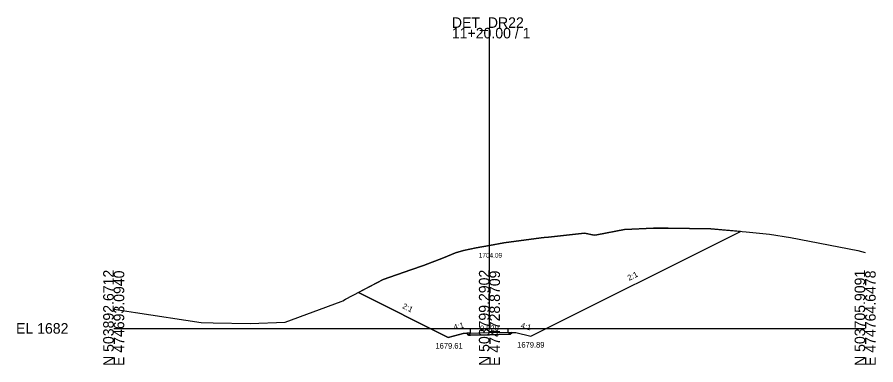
# Model space of a CAD drawing. Extents: x -26 to 1203, y -10 to 9633.
# Drawn here: x -25.7 to 202.8, y 2990.3 to 3082.8 of the extents above; entities that cross this region are included whole.
import ezdxf

# ---------------------------------------------------------------- set-up
doc = ezdxf.new("R2010")
doc.units = 0
for name, color, linetype in [('Exist Cross Section Cell', 7, 'Continuous'), ('Exist XS Center Line Elevation Label', 7, 'Continuous'), ('Exist XS Ground Line', 7, 'Continuous'), ('Prop XS Ditch Slope Text', 7, 'Continuous'), ('Prop XS Ditch Standard Text', 7, 'Continuous'), ('Prop XS Earthwork Shape', 7, 'Continuous'), ('Prop XS EOT Tick Mark', 7, 'Continuous'), ('Prop XS Finish Grade', 7, 'Continuous'), ('Prop XS Finish Grade Earthwork', 7, 'Continuous'), ('Prop XS Finish Grade Pavement', 7, 'Continuous'), ('Prop XS Pvmt Edge Slope', 7, 'Continuous'), ('Prop XS SE Text', 7, 'Continuous'), ('Prop XS Shoulder Borrow Shape', 7, 'Continuous'), ('Prop XS Side Slope Text', 7, 'Continuous'), ('Prop XS Subgrade Earthwork', 7, 'Continuous')]:
    doc.layers.add(name, color=color, linetype=linetype)

msp = doc.modelspace()

# ---------------------------------------------------------------- linework, layer by layer
at = {"layer": 'Exist Cross Section Cell'}
for p, q in [((100, 3000), (100, 3079.98)), ((0, 3000), (100, 3000)), ((100, 3000), (200, 3000))]:
    msp.add_line(p, q, dxfattribs=at)
at = {"layer": 'Exist XS Ground Line'}
msp.add_lwpolyline([(0, 3005.15), (5.82, 3004.23), (23.26, 3001.59), (26.46, 3001.48), (36.33, 3001.31), (45.67, 3001.68), (60.56, 3007.17), (60.99, 3007.35), (61.71, 3007.74), (71.7, 3013.04), (79.08, 3015.55), (82.41, 3016.78), (87.78, 3018.79), (90.98, 3020.09), (93.12, 3020.74), (96.44, 3021.44), (100, 3022.09), (103.83, 3022.8), (113.8, 3024.06), (114.54, 3024.17), (115.74, 3024.26), (125.26, 3025.31), (127.85, 3024.82), (128.6, 3024.93), (135.97, 3026.35), (143.69, 3026.65), (146.26, 3026.66), (147.53, 3026.64), (158.95, 3026.5), (168.35, 3025.67), (174.54, 3025.12), (180.1, 3024.19), (198.03, 3020.69), (200, 3020.24)], dxfattribs=at)
at = {"layer": 'Prop XS Earthwork Shape'}
msp.add_lwpolyline([(105.53, 2998.44), (106.02, 2998.93), (107, 2998.89), (111, 2997.89), (166.83, 3025.8), (158.95, 3026.5), (147.53, 3026.64), (146.26, 3026.66), (143.69, 3026.65), (135.97, 3026.35), (128.6, 3024.93), (127.85, 3024.82), (125.26, 3025.31), (115.74, 3024.26), (114.54, 3024.17), (113.8, 3024.06), (103.83, 3022.8), (100, 3022.09), (96.44, 3021.44), (93.12, 3020.74), (90.98, 3020.09), (87.78, 3018.79), (82.41, 3016.78), (79.08, 3015.55), (71.7, 3013.04), (65.12, 3009.55), (89, 2997.61), (93, 2998.61), (93.98, 2998.69), (94.45, 2998.22), (95, 2998.23), (100, 2998.33), (105, 2998.43)], close=True, dxfattribs=at)
at = {"layer": 'Prop XS EOT Tick Mark'}
for p, q in [((95, 2998.77), (95, 2999.77)), ((105, 2998.97), (105, 2999.97))]:
    msp.add_line(p, q, dxfattribs=at)
at = {"layer": 'Prop XS Finish Grade'}
for p, q in [((95, 2998.77), (93.98, 2998.69)), ((105, 2998.97), (106.02, 2998.93))]:
    msp.add_line(p, q, dxfattribs=at)
at = {"layer": 'Prop XS Finish Grade Earthwork'}
for p, q in [((111, 2997.89), (166.83, 3025.8)), ((89, 2997.61), (65.12, 3009.55)), ((93, 2998.61), (89, 2997.61)), ((93.98, 2998.69), (93, 2998.61)), ((106.02, 2998.93), (107, 2998.89)), ((107, 2998.89), (111, 2997.89))]:
    msp.add_line(p, q, dxfattribs=at)
at = {"layer": 'Prop XS Finish Grade Pavement'}
for p, q in [((95, 2998.77), (100, 2998.87)), ((100, 2998.87), (105, 2998.97))]:
    msp.add_line(p, q, dxfattribs=at)
at = {"layer": 'Prop XS Pvmt Edge Slope'}
for p, q in [((95, 2998.77), (94.45, 2998.22)), ((105, 2998.97), (105.53, 2998.44))]:
    msp.add_line(p, q, dxfattribs=at)
at = {"layer": 'Prop XS Shoulder Borrow Shape'}
for points in [[(95, 2998.77), (93.98, 2998.69), (94.45, 2998.22)], [(105, 2998.97), (106.02, 2998.93), (105.53, 2998.44)]]:
    msp.add_lwpolyline(points, close=True, dxfattribs=at)
at = {"layer": 'Prop XS Subgrade Earthwork'}
for p, q in [((94.45, 2998.22), (93.98, 2998.69)), ((105, 2998.43), (100, 2998.33)), ((105, 2998.43), (105.53, 2998.44)), ((105.53, 2998.44), (106.02, 2998.93)), ((95, 2998.23), (94.45, 2998.22)), ((100, 2998.33), (95, 2998.23))]:
    msp.add_line(p, q, dxfattribs=at)

# ---------------------------------------------------------------- texts
at = {"layer": 'Exist Cross Section Cell'}
for s, p in [('DET_DR22', (90, 3079.98)), ('11+20.00 / 1', (90, 3077.18)), ('EL 1682', (-26, 2998.6))]:
    msp.add_text(s, height=2.8, dxfattribs=at).set_placement(p)
for s, p in [('N 503892.6712', (0, 2990)), ('E 474693.0940', (2.8, 2990)), ('N 503799.2902', (100, 2990)), ('E 474728.8709', (102.8, 2990)), ('N 503705.9091', (200, 2990)), ('E 474764.6478', (202.8, 2990))]:
    msp.add_text(s, height=2.8, rotation=90, dxfattribs=at).set_placement(p)
at = {"layer": 'Exist XS Center Line Elevation Label'}
msp.add_text('1704.09', height=1.25, dxfattribs=at).set_placement((97.15, 3018.84))
at = {"layer": 'Prop XS Ditch Slope Text'}
for rotation, p in [(14.0362, (90.64, 2999.56)), (345.9638, (108.21, 3000.13))]:
    msp.add_text('4:1', height=1.5, rotation=rotation, dxfattribs=at).set_placement(p)
at = {"layer": 'Prop XS Ditch Standard Text'}
for s, p in [('1679.61', (85.64, 2994.61)), ('1679.89', (107.39, 2994.89))]:
    msp.add_text(s, height=1.5, dxfattribs=at).set_placement(p)
at = {"layer": 'Prop XS SE Text'}
msp.add_text('0.020', height=1.5, rotation=1.1458, dxfattribs=at).set_placement((97.5, 2999.25))
at = {"layer": 'Prop XS Side Slope Text'}
for rotation, p in [(26.5651, (137.18, 3012.65)), (333.4349, (76.67, 3005.45))]:
    msp.add_text('2:1', height=1.5, rotation=rotation, dxfattribs=at).set_placement(p)

doc.saveas('drawing.dxf')
